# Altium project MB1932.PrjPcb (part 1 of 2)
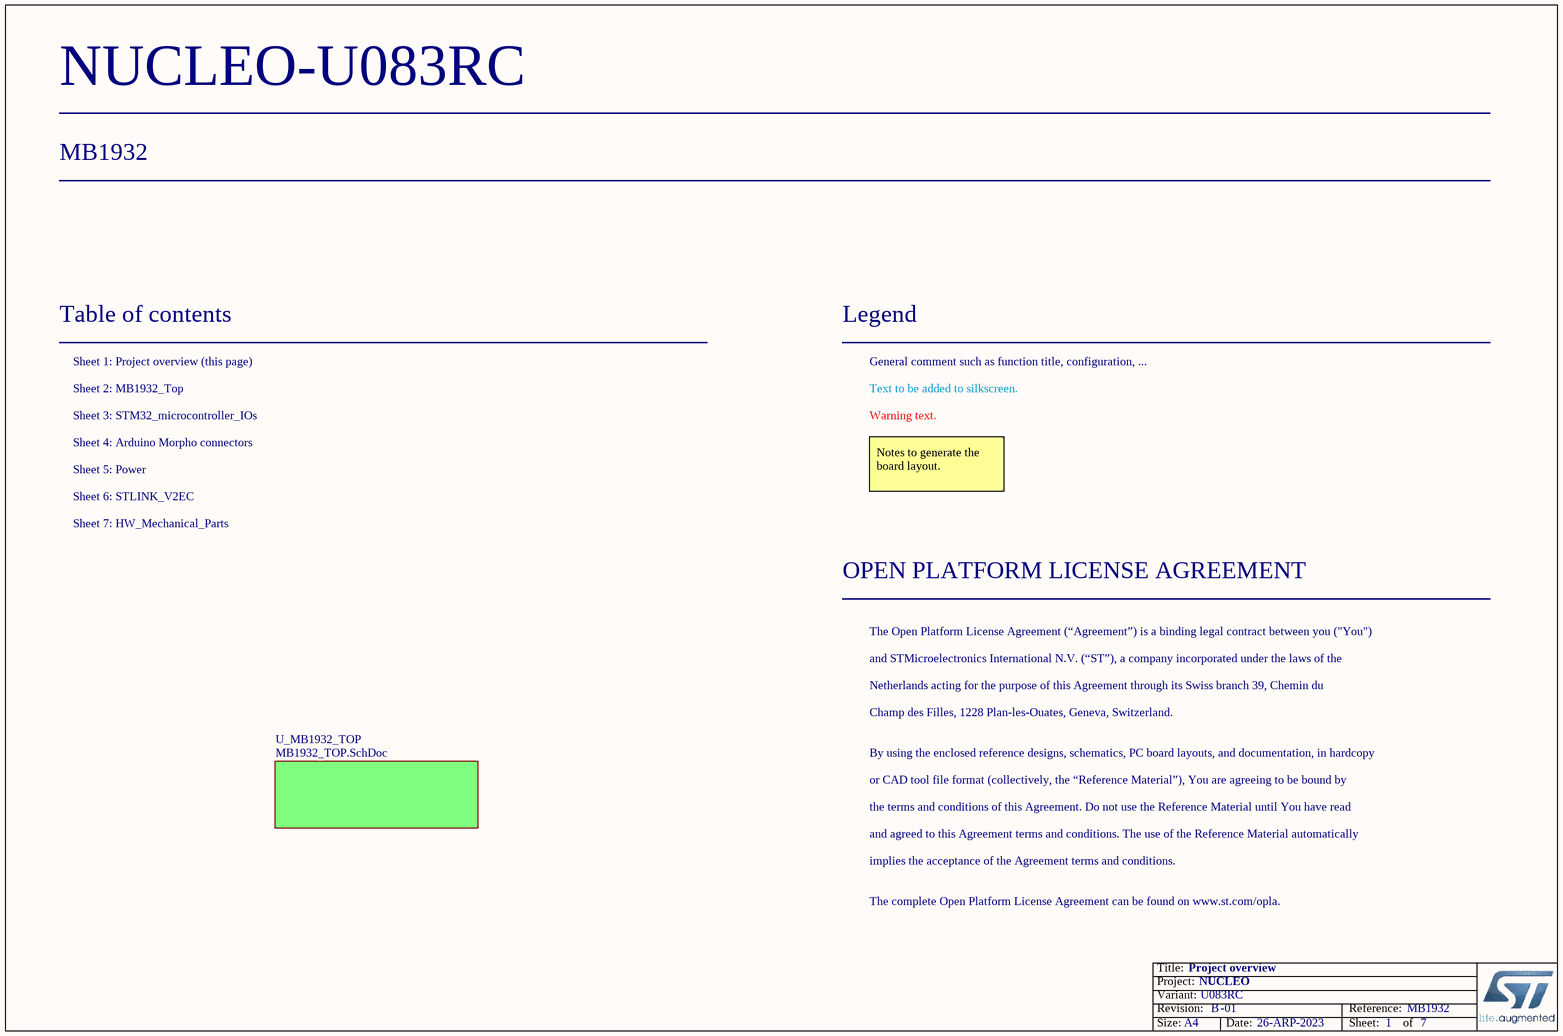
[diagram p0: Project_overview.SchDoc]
VariantName: U083RC; Board_Reference: MB1932; Board_PCB_Revision: B; Board_Name: NUCLEO; Board_Document_Date: 26-ARP-2023; Board_Assembly_Revision: 01
7 sheets, 197 parts. Net scope: flat (ports and power ports of the same name join across sheets).
Board file: MB1932.PcbDoc
Sheets:
  Project_overview.SchDoc
    U_MB1932_TOP = MB1932_TOP.SchDoc
      Power = Power.SchDoc
      HW_Mechanical_Parts = HW_Mechanical_Parts.SchDoc
      U_STM32_microcontroller_IOs = STM32_microcontroller_IOs.SchDoc
      U_Arduino_Morpho_connectors = Arduino_Morpho_connectors.SchDoc
      U_STLINK_V2EC = STLINK_V2EC.SchDoc

## Sheet Project_overview.SchDoc: Project overview
size A4; Date: Not used; ApprovedBy: Not used; CheckedBy: Not used; Author: Not used; CompanyName: STMicroelectronics; DrawnBy: Not used; Engineer: Not used; Organization: Not used; Address1: Not used; Address2: Not used; Address3: Not used; Address4: Not used; DocumentNumber: 1; Revision: Not used; SheetNumber: 1; SheetTotal: 7

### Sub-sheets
U_MB1932_TOP = MB1932_TOP.SchDoc: no entries

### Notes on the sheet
- Table of contents
- Sheet 1: Project overview (this page)
- Legend
- General comment such as function title, configuration, ...
- Sheet 2: MB1932_Top
- Sheet 4: Arduino Morpho connectors
- Sheet 3: STM32_microcontroller_IOs
- Text to be added to silkscreen.
- Warning text.
- Sheet 5: Power
- Sheet 6: STLINK_V2EC
- Notes to generate the board layout.
- Sheet 7: HW_Mechanical_Parts
- OPEN PLATFORM LICENSE AGREEMENT
- The Open Platform License Agreement (“Agreement”) is a binding legal contract between you ("You")
- and STMicroelectronics International N.V. (“ST”), a company incorporated under the laws of the
- Netherlands acting for the purpose of this Agreement through its Swiss branch 39, Chemin du
- Champ des Filles, 1228 Plan-les-Ouates, Geneva, Switzerland.
- By using the enclosed reference designs, schematics, PC board layouts, and documentation, in hardcopy
- or CAD tool file format (collectively, the “Reference Material”), You are agreeing to be bound by
- the terms and conditions of this Agreement. Do not use the Reference Material until You have read
- and agreed to this Agreement terms and conditions. The use of the Reference Material automatically
- implies the acceptance of the Agreement terms and conditions.
- The complete Open Platform License Agreement can be found on www.st.com/opla.

## Sheet MB1932_TOP.SchDoc: TOP
size A4; CompanyName: STMicroelectronics; Organization: Microcontrollers Division; SheetNumber: 2; SheetTotal: 7
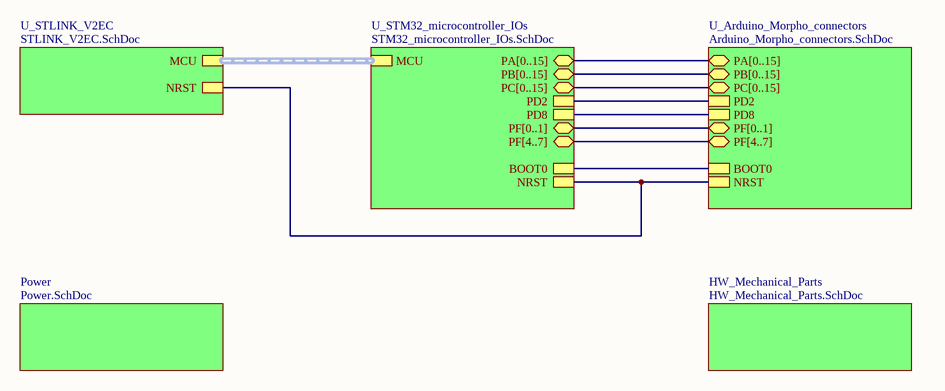
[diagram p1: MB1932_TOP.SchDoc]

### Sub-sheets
HW_Mechanical_Parts = HW_Mechanical_Parts.SchDoc: no entries
Power = Power.SchDoc: no entries
U_Arduino_Morpho_connectors = Arduino_Morpho_connectors.SchDoc: NRST, PA[0..15] (bidir), PB[0..15] (bidir), PD2, PC[0..15] (bidir), PD8, PF[4..7] (bidir), BOOT0, PF[0..1] (bidir)
U_STLINK_V2EC = STLINK_V2EC.SchDoc: MCU (harness MCU), NRST
U_STM32_microcontroller_IOs = STM32_microcontroller_IOs.SchDoc: PA[0..15] (bidir), PB[0..15] (bidir), PD2, PC[0..15] (bidir), MCU (harness MCU), PF[0..1] (bidir), PF[4..7] (bidir), BOOT0, PD8, NRST

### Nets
(unnamed): sheet U_STM32_microcontroller_IOs/PD2, sheet U_Arduino_Morpho_connectors/PD2
(unnamed): sheet U_STM32_microcontroller_IOs/BOOT0, sheet U_Arduino_Morpho_connectors/BOOT0  [a separate net that carries the same name]
(unnamed): sheet U_STM32_microcontroller_IOs/PD8, sheet U_Arduino_Morpho_connectors/PD8  [a separate net that carries the same name]
(unnamed): sheet U_STM32_microcontroller_IOs/NRST, sheet U_Arduino_Morpho_connectors/NRST, sheet U_STLINK_V2EC/NRST  [a separate net that carries the same name]

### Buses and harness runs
bus sheet U_Arduino_Morpho_connectors/PA[0..15] = sheet U_STM32_microcontroller_IOs/PA[0..15]
bus sheet U_Arduino_Morpho_connectors/PB[0..15] = sheet U_STM32_microcontroller_IOs/PB[0..15]
bus sheet U_Arduino_Morpho_connectors/PC[0..15] = sheet U_STM32_microcontroller_IOs/PC[0..15]
bus sheet U_Arduino_Morpho_connectors/PF[0..1] = sheet U_STM32_microcontroller_IOs/PF[0..1]
bus sheet U_Arduino_Morpho_connectors/PF[4..7] = sheet U_STM32_microcontroller_IOs/PF[4..7]
harness sheet U_STLINK_V2EC/MCU = sheet U_STM32_microcontroller_IOs/MCU

## Sheet Power.SchDoc: Power
size A4; CompanyName: STMicroelectronics; Organization: Microcontrollers Division; SheetNumber: 5; SheetTotal: 7
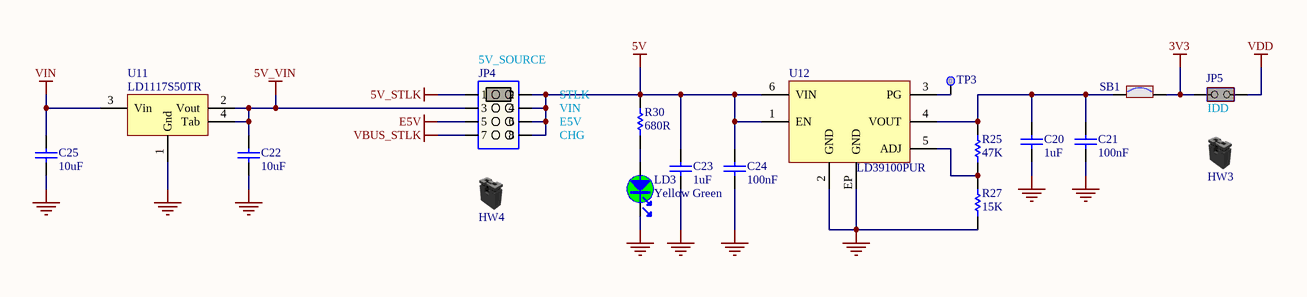
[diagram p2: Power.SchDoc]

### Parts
C20  value 1uF  [C0603]  (hidden comment: Capacitor)
C21  value 100nF  [C0402]  (hidden comment: Capacitor)
C22  value 10uF  [C0805]  (hidden comment: Capacitor)
C23  value 1uF  [C0603]  (hidden comment: Capacitor)
C24  value 100nF  [C0402]  (hidden comment: Capacitor)
C25  value 10uF  [C0805]  (hidden comment: Capacitor)
HW3  Shunt Black 2.54mm  (value not drawn)  (mechanical)
HW4  Shunt Black 2.54mm  (value not drawn)  (mechanical)
JP4  Jumper_Header 4x2 Fitted 1-2  [CON_SAMTEC_TSW-104-07-X-D]  (value not drawn)
JP5  Jumper_Header 2x1 Fitted  [CON_SAMTEC_TSW-102-07-G-S]  (value not drawn)
LD3  value Yellow Green  [LED_0402_EVERLIGHT_16-213SYGC/S530-E3-TR8 _YELLOW-GREEN_1A2K_H0P45]  (hidden comment: LED_green)
R25  value 47K  [R0402]  (hidden comment: Resistor)
R27  value 15K  [R0402]  (hidden comment: Resistor)
R30  value 680R  [R0402]  (hidden comment: Resistor)
SB1  SB_ON  [SOLDER-BRIDGE_R0603-0R]  (value not drawn)
TP3  Test Point  [TP_SMD_1MM]  (value not drawn)  (no BOM)
U11  LD1117S50TR  [REG_SOT223-TAB]
U12  LD39100PUR  [ICC_DFN6-EPAD_3X3_P095]

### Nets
3V3: JP5.2(NO) SB1.2
5V: C23.2 C24.2 JP4.2 JP4.4 JP4.6 JP4.8 R30.1 U12.1(EN) U12.6(VIN)
5V_STLK: JP4.1
5V_VIN: C22.2 JP4.3 U11.2(Vout) U11.4(Tab)
E5V: JP4.5
GND: C20.1 C21.1 C22.1 C23.1 C24.1 C25.1 LD3.2 R27.1 U11.1(Gnd) U12.2(GND) U12.EP(GND)
VBUS_STLK: JP4.7
VDD: JP5.1(COMMON)
VIN: C25.2 U11.3(Vin)
NetC20_2: C20.2 C21.2 R25.2 SB1.1 U12.4(VOUT)
NetLD3_1: LD3.1 R30.2
NetR25_1: R25.1 R27.2 U12.5(ADJ)
NetTP3_1: TP3.1 U12.3(PG)

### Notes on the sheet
- (near JP4) 5V_SOURCE
- CHG
- E5V
- VIN
- STLK
- (near JP5) IDD

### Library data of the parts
C20 C23 = MCD-00010: Capacitor, MLCC, 1uF, 16V, X5R, +/-10%, 0603, T=0.8mm; Manufacturer_Part_Number: CC0603KRX5R7BB105; Manufacturer: YAGEO; Alternate_Manufacturer_Part_Number: GCM155R71C104KA55D; Alternate_Manufacturer: MURATA; Part_Preference: Recommended; ECCN_US: EAR99; ECCN_EU: NEC; Provided_By: SUBCO; Component_Country_Of_Origin: China; ShowFields: YES; ID: 2470
C21 C24 = MCD-00006: Capacitor, MLCC, 100nF, 16V, X7R, +/-10%, 0402, T=0.5mm; Manufacturer_Part_Number: CC0402KRX7R7BB104; Manufacturer: YAGEO; Alternate_Manufacturer_Part_Number: GCM155R71C104KA55D; Alternate_Manufacturer: MURATA; Part_Preference: Recommended; ECCN_US: EAR99; ECCN_EU: NEC; Provided_By: SUBCO; Order_Code_RS: 616-9701; Component_Country_Of_Origin: China; ShowFields: YES; ID: 2474
C22 C25 = MCD-00014: Capacitor, MLCC, 10uF, 25V, X5R, +/-10%, 0805, T=0.85mm; Manufacturer_Part_Number: CC0805KRX5R8BB106; Manufacturer: YAGEO; Alternate_Manufacturer_Part_Number: GCM155R71C104KA55D; Alternate_Manufacturer: MURATA; Part_Preference: Recommended; Full_Alternate_Internal_Part_Number: MCD-02385; Partial_Alternate_Internal_Part_Number: MCD-03053; ECCN_US: EAR99; ECCN_EU: NEC; Provided_By: SUBCO; Component_Country_Of_Origin: China; ShowFields: YES; ID: 2468
HW3 HW4 = MCD-00043: SHUNT 2.54mm BLACK; Manufacturer_Part_Number: SNT-100-BK-G; Manufacturer: SAMTEC; Part_Type: Misc; Part_Preference: Recommended; Full_Alternate_Internal_Part_Number: MCD-02388; Value: SNT-100-BK-G; Component_Country_Of_Origin: China, Costa Rica, Malaysia, United States, Vietnam; ShowFields: YES; ID: 2551
JP4 = MCD-00686: Header, 4x2, 2.54mm, VR, TH, T=5.84mm/2.54mm; Part_Type: Connector; Manufacturer_Part_Number: TSW-104-07-G-D; Manufacturer: SAMTEC; Part_Preference: Recommended; Order_Code_RS: 161-2260; Component_Country_Of_Origin: China, Costa Rica, Malaysia, United States, Vietnam; ShowFields: YES; ID: 3062
JP5 = MCD-00683: Header, 2x1, 2.54mm, VR, TH, T=5.84mm/2.54mm; Part_Type: Connector; Manufacturer_Part_Number: TSW-102-07-G-S; Manufacturer: SAMTEC; Alternate_Manufacturer_Part_Number: 313102S111116; Alternate_Manufacturer: LIANYI; Part_Preference: Recommended; Full_Alternate_Internal_Part_Number: MCD-02389; Partial_Alternate_Internal_Part_Number: MCD-02957; Provided_By: SUBCO; Order_Code_RS: 155-5312; Component_Country_Of_Origin: China, Costa Rica, Malaysia, United States, Vietnam; ShowFields: YES; ID: 3057
LD3 = MCD-02330: LED, Yellow Green, 2V, 25mA, 0402, 0.45mm; Part_Type: Display; Manufacturer_Part_Number: 16-213SYGC/S530-E3/TR8; Manufacturer: EVERLIGHT; Alternate_Manufacturer_Part_Number: LG Q396-PS-35; Alternate_Manufacturer: OSRAM OPTO SEMICONDUCTORS; Part_Preference: Recommended; Provided_By: SUBCO; Component_Country_Of_Origin: China; ShowFields: YES; ID: 4436
R25 = MCD-00063: Resistor, 47K, 0402, +/-1%, 1/16W; Part_Preference: Recommended; Manufacturer: YAGEO; Manufacturer_Part_Number: RC0402FR-0747KL; Component_Country_Of_Origin: China; ShowFields: YES; ID: 2528
R27 = MCD-01943: Resistor, 15K, 0402, +/-1%, 1/16W; Part_Preference: Recommended; Manufacturer: YAGEO; Manufacturer_Part_Number: RC0402FR-0715KL; Order_Code_RS: 618-6009; Component_Country_Of_Origin: China; ShowFields: YES; ID: 4043
R30 = MCD-00507: Resistor, 680R, 0402, +/-1%, 1/16W; Manufacturer_Part_Number: RC0402FR-07680RL; Manufacturer: YAGEO; Alternate_Manufacturer_Part_Number: RT0402FRE07100KL; Part_Preference: Recommended; ECCN_US: EAR99; ECCN_EU: NEC; Provided_By: SUBCO; Component_Country_Of_Origin: China; ShowFields: YES; ID: 3238
SB1 = MCD-00071: Solder Bridge ON; Part_Type: Misc; Manufacturer_Part_Number: RC0603JR-070RL; Manufacturer: YAGEO; Part_Preference: Recommended; Provided_By: SUBCO; ShowFields: YES; ID: 2521
TP3 = MCD-00074: Test Point 1mm; Part_Type: Misc; Part_Preference: Recommended; ShowFields: YES; ID: 2518
U11 = MCD-00088: IC REG LDO 5V 0.8A SOT223; Manufacturer: STMICROELECTRONICS; BMS_Part_Number: 9176133; Part_Preference: Recommended; Manufacturer_HQ_COO: EU; ECCN_US: EAR99; ECCN_EU: NEC; Provided_By: SUBCO with ST control; Component_Country_Of_Origin: China; ShowFields: YES; ID: 2503
U12 = MCD-03339: LDO, output 1.5 to 5.5V 1A adjustable; Part_Type: IC; Part_Preference: Recommended; Manufacturer: STMICROELECTRONICS; ShowFields: YES; ID: 5455

## Sheet HW_Mechanical_Parts.SchDoc: HW Mechanical parts
size A4; SheetNumber: 7; SheetTotal: 7
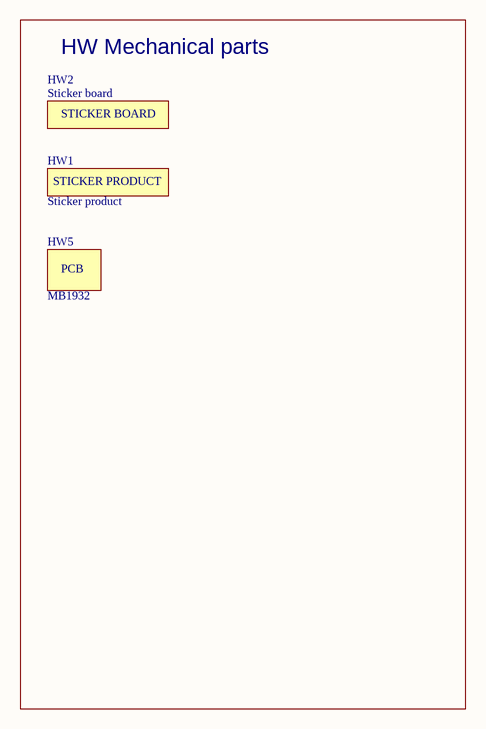
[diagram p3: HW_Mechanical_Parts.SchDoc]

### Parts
HW1  value Sticker product  [STICKER_PRODUCT_25X9]  (hidden comment: STICKER_PRODUCT)  (no BOM)
HW2  value Sticker board  [STICKER_BOARD_25X9]  (hidden comment: STICKER_BOARD)  (no BOM)
HW5  value MB1932  (hidden comment: PCB)  (no BOM)

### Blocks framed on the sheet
HW Mechanical parts: HW1 HW2 HW5

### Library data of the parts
HW1 = MCD-00547: Sticker product 25x9 mm; Part_Type: Misc; Part_Preference: Recommended; ShowFields: YES; ID: 3197
HW2 = MCD-00235: Sticker Board 25x9 mm; Part_Type: Misc; Part_Preference: Recommended; ShowFields: YES; ID: 2632
HW5 = MCD-03167: MB1932 PCB; Part_Preference: Recommended; ShowFields: YES; ID: 5283

## Sheet STM32_microcontroller_IOs.SchDoc: STM32_microcontroller_IOs
size A4; CompanyName: STMicroelectronics; Organization: Microcontrollers Division; SheetNumber: 3; SheetTotal: 7
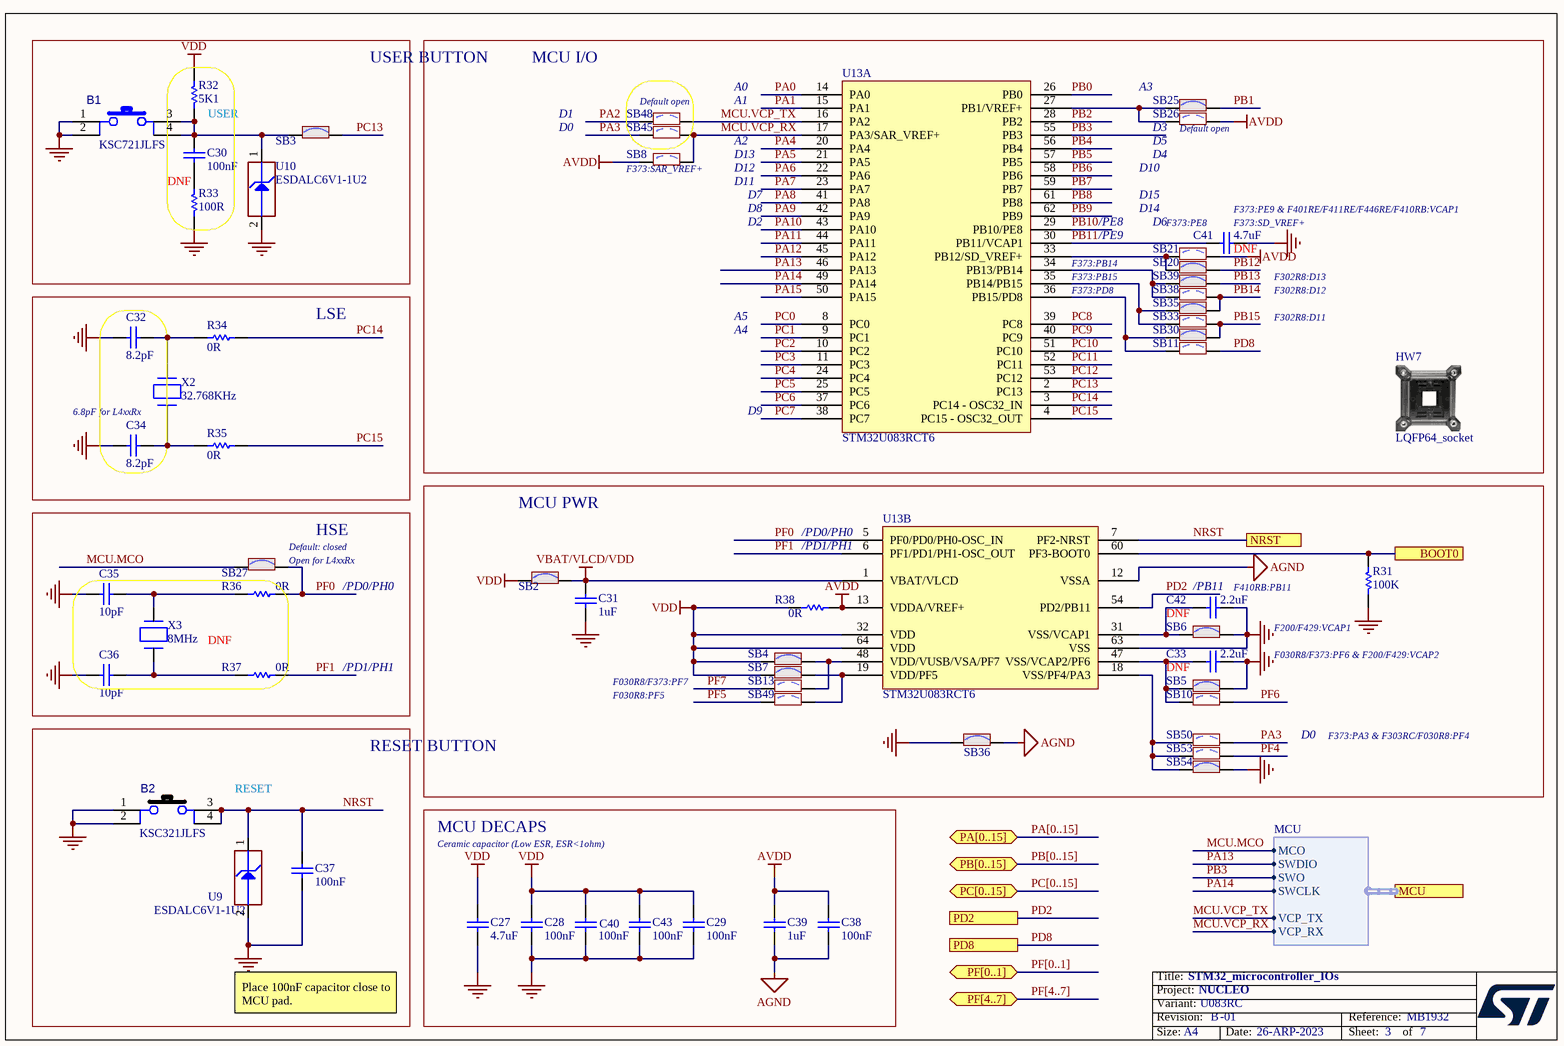
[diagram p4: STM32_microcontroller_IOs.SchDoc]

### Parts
B1  value KSC721JLFS  [SWI_C&K_KSC721JLFS_BLUE]  (hidden comment: SW_BLUE_KSC721JLFS)
B2  value KSC321JLFS  [SWI_C&K_KSC321JLFS_BLACK]  (hidden comment: SW_BLACK_KSC321JLFS)
C27  value 4.7uF  [C0603_H0P8]  (hidden comment: Capacitor)
C28  value 100nF  [C0402]  (hidden comment: Capacitor)
C29  value 100nF  [C0402]  (hidden comment: Capacitor)
C30  value 100nF  [C0402]  (hidden comment: Capacitor)
C31  value 1uF  [C0603]  (hidden comment: Capacitor)
C32  value 8.2pF  [C0402]  (hidden comment: Capacitor)
C33  value 2.2uF  [C0402]  (hidden comment: Capacitor)
C34  value 8.2pF  [C0402]  (hidden comment: Capacitor)
C35  value 10pF  [C0402]  (hidden comment: Capacitor)
C36  value 10pF  [C0402]  (hidden comment: Capacitor)
C37  value 100nF  [C0402]  (hidden comment: Capacitor)
C38  value 100nF  [C0402]  (hidden comment: Capacitor)
C39  value 1uF  [C0603]  (hidden comment: Capacitor)
C40  value 100nF  [C0402]  (hidden comment: Capacitor)
C41  value 4.7uF  [C0603_H0P8]  (hidden comment: Capacitor)
C42  value 2.2uF  [C0402]  (hidden comment: Capacitor)
C43  value 100nF  [C0402]  (hidden comment: Capacitor)
HW7  value LQFP64_socket  (hidden comment: SOCKET_LQFP64)  (mechanical)
R31  value 100K  [R0402]  (hidden comment: Resistor)
R32  value 5K1  [R0402]  (hidden comment: Resistor)
R33  value 100R  [R0402]  (hidden comment: Resistor)
R34  value 0R  [R0402]  (hidden comment: Resistor)
R35  value 0R  [R0402]  (hidden comment: Resistor)
R36  value 0R  [R0402]  (hidden comment: Resistor)
R37  value 0R  [R0402]  (hidden comment: Resistor)
R38  value 0R  [R0603]  (hidden comment: Resistor)
SB2  SB_ON  [SOLDER-BRIDGE_R0603-0R]  (value not drawn)
SB3  SB_ON  [SOLDER-BRIDGE_R0603-0R]  (value not drawn)
SB4  SB_ON  [SOLDER-BRIDGE_R0603-0R]  (value not drawn)
SB5  SB_ON  [SOLDER-BRIDGE_R0603-0R]  (value not drawn)
SB6  SB_ON  [SOLDER-BRIDGE_R0603-0R]  (value not drawn)
SB7  SB_ON  [SOLDER-BRIDGE_R0603-0R]  (value not drawn)
SB8  SB_OFF  [SOLDER-BRIDGE_R0603-0R]  (value not drawn)
SB10  SB_OFF  [SOLDER-BRIDGE_R0603-0R]  (value not drawn)
SB11  SB_OFF  [SOLDER-BRIDGE_R0603-0R]  (value not drawn)
SB13  SB_OFF  [SOLDER-BRIDGE_R0603-0R]  (value not drawn)
SB20  SB_ON  [SOLDER-BRIDGE_R0603-0R]  (value not drawn)
SB21  SB_OFF  [SOLDER-BRIDGE_R0603-0R]  (value not drawn)
SB25  SB_ON  [SOLDER-BRIDGE_R0603-0R]  (value not drawn)
SB26  SB_OFF  [SOLDER-BRIDGE_R0603-0R]  (value not drawn)
SB27  SB_ON  [SOLDER-BRIDGE_R0603-0R]  (value not drawn)
SB30  SB_ON  [SOLDER-BRIDGE_R0603-0R]  (value not drawn)
SB33  SB_OFF  [SOLDER-BRIDGE_R0603-0R]  (value not drawn)
SB35  SB_ON  [SOLDER-BRIDGE_R0603-0R]  (value not drawn)
SB36  SB_ON  [SOLDER-BRIDGE_R0603-0R]  (value not drawn)
SB38  SB_OFF  [SOLDER-BRIDGE_R0603-0R]  (value not drawn)
SB39  SB_ON  [SOLDER-BRIDGE_R0603-0R]  (value not drawn)
SB45  SB_OFF  [SOLDER-BRIDGE_R0603-0R]  (value not drawn)
SB48  SB_OFF  [SOLDER-BRIDGE_R0603-0R]  (value not drawn)
SB49  SB_OFF  [SOLDER-BRIDGE_R0603-0R]  (value not drawn)
SB50  SB_OFF  [SOLDER-BRIDGE_R0603-0R]  (value not drawn)
SB53  SB_OFF  [SOLDER-BRIDGE_R0603-0R]  (value not drawn)
SB54  SB_ON  [SOLDER-BRIDGE_R0603-0R]  (value not drawn)
U9  value ESDALC6V1-1U2  [ESD_ST0201]  (hidden comment: ESD-TRANSIL)
U10  value ESDALC6V1-1U2  [ESD_ST0201]  (hidden comment: ESD-TRANSIL)
U13  value STM32U083RCT6  [ICC_LQFP64_10X10_P050_SOCKET_YAMAICHI_IC149-064-069-B5_NM]  (hidden comment: STM32_MCU_LQFP64)  (parts A,B of 2)
X2  value 32.768KHz  [CRY_NX2012SA_2P]  (hidden comment: XTAL_2_PINS)
X3  value 8MHz  [CRY_NX3225GD_2P]  (hidden comment: XTAL_2_PINS)

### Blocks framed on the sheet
USER BUTTON: B1 C30 R32 R33 SB3 U10
MCU I/O: C41 HW7 SB8 SB11 SB20 SB21 SB25 SB26 SB30 SB33 SB35 SB38 SB39 U13
Default open: SB45 SB48
LSE: C32 C34 R34 R35 X2
HSE: SB27
MCU PWR: C31 C33 C42 R31 R38 SB2 SB4-SB7 SB10 SB13 SB36 SB49 SB50 SB53 SB54 U13
DNF: C35 C36 R36 R37 X3
RESET BUTTON: B2 C37 U9
MCU DECAPS: C27-C29 C38-C40 C43

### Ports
BOOT0, MCU (harness MCU), NRST, PA[0..15] (bidir), PB[0..15] (bidir), PC[0..15] (bidir), PD2, PD8, PF[0..1] (bidir), PF[4..7] (bidir)

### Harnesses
MCU: MCO, SWDIO, SWO, VCP_TX, SWCLK, VCP_RX

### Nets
AGND: C38.1 C39.2 SB36.2 U13.12(VSSA)
AVDD: C38.2 C39.1 R38.2 SB8.1 SB21.2 SB26.2 U13.13(VDDA/VREF+)
GND: B1.1 B1.2 B2.1 B2.2 C27.1 C28.1 C29.1 C31.2 C32.1 C33.2 C34.1 C35.1 C36.1 C37.1 C40.1 C41.2 C42.2 C43.1 R31.2 R33.2 SB5.2 SB6.2 SB36.1 SB54.2 U9.2(GND) U10.2(GND) U13.63(VSS)
VBAT/VLCD/VDD: C31.1 SB2.2 U13.1(VBAT/VLCD)
VDD: C27.2 C28.2 C29.2 C40.2 C43.2 R32.2 R38.1 SB2.1 SB4.1 SB7.1 U13.32(VDD) U13.64(VDD)
BOOT0: R31.1 U13.60(PF3-BOOT0) ; port BOOT0
MCU.MCO: SB27.1 ; port MCU.MCO
MCU.VCP_RX: SB8.2 SB45.2 U13.17(PA3/SAR_VREF+) ; port MCU.VCP_RX
MCU.VCP_TX: SB48.2 U13.16(PA2) ; port MCU.VCP_TX
NRST: B2.3 B2.4 C37.2 U9.1(IO1) U13.7(PF2-NRST) ; port NRST
PA0: U13.14(PA0)
PA1: U13.15(PA1)
PA2: SB48.1
PA3: SB45.1 SB50.2
PA4: U13.20(PA4)
PA5: U13.21(PA5)
PA6: U13.22(PA6)
PA7: U13.23(PA7)
PA8: U13.41(PA8)
PA9: U13.42(PA9)
PA10: U13.43(PA10)
PA11: U13.44(PA11)
PA12: U13.45(PA12)
PA13: U13.46(PA13) ; port MCU.SWDIO  [project net MCU.SWDIO]
PA14: U13.49(PA14) ; port MCU.SWCLK  [project net MCU.SWCLK]
PA15: U13.50(PA15)
PB0: U13.26(PB0)
PB1: SB25.2
PB2: U13.28(PB2)
PB3: U13.55(PB3) ; port MCU.SWO  [project net MCU.SWO]
PB4: U13.56(PB4)
PB5: U13.57(PB5)
PB6: U13.58(PB6)
PB7: U13.59(PB7)
PB8: U13.61(PB8)
PB9: U13.62(PB9)
PB10: U13.29(PB10/PE8)
PB11: C41.1 U13.30(PB11/VCAP1)
PB12: SB20.2
PB13: SB39.2
PB14: SB35.2 SB38.2
PB15: SB30.2 SB33.2
PC0: U13.8(PC0)
PC1: U13.9(PC1)
PC2: U13.10(PC2)
PC3: U13.11(PC3)
PC4: U13.24(PC4)
PC5: U13.25(PC5)
PC6: U13.37(PC6)
PC7: U13.38(PC7)
PC8: U13.39(PC8)
PC9: U13.40(PC9)
PC10: U13.51(PC10)
PC11: U13.52(PC11)
PC12: U13.53(PC12)
PC13: SB3.2 U13.2(PC13)
PC14: R34.2 U13.3(PC14_-_OSC32_IN)
PC15: R35.2 U13.4(PC15_-_OSC32_OUT)
PD2: U13.54(PD2/PB11) ; port PD2
PD8: SB11.2 ; port PD8
PF0: R36.2 SB27.2 U13.5(PF0/PD0/PH0-OSC_IN)
PF1: R37.2 U13.6(PF1/PD1/PH1-OSC_OUT)
PF4: SB53.2
PF5: SB49.1
PF6: SB10.2
PF7: SB13.1
NetB1_3: B1.3 B1.4 C30.2 R32.1 SB3.1 U10.1(IO1)
NetC30_1: C30.1 R33.1
NetC32_2: C32.2 R34.1 X2.2(X2)
NetC33_1: C33.1 SB5.1 SB10.1 U13.47(VSS/VCAP2/PF6)
NetC34_2: C34.2 R35.1 X2.1(X1)
NetC35_2: C35.2 R36.1 X3.2(X2)
NetC36_2: C36.2 R37.1 X3.1(X1)
NetC42_1: C42.1 SB6.1 U13.31(VSS/VCAP1)
NetSB4_2: SB4.2 SB13.2 U13.48(VDD/VUSB/VSA/PF7)
NetSB7_2: SB7.2 SB49.2 U13.19(VDD/PF5)
NetSB11_1: SB11.1 SB30.1 U13.36(PB15/PD8)
NetSB20_1: SB20.1 SB21.1 U13.33(PB12/SD_VREF+)
NetSB25_1: SB25.1 SB26.1 U13.27(PB1/VREF+)
NetSB33_1: SB33.1 SB35.1 U13.35(PB14/PB15)
NetSB38_1: SB38.1 SB39.1 U13.34(PB13/PB14)
NetSB50_1: SB50.1 SB53.1 SB54.1 U13.18(VSS/PF4/PA3)

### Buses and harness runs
bus PA[0..15] = port PA[0..15]
bus PB[0..15] = port PB[0..15]
bus PC[0..15] = port PC[0..15]
bus PF[0..1] = port PF[0..1]
bus PF[4..7] = port PF[4..7]

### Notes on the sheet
- (near R32) USER
- D1
- A0
- A1
- A3
- DNF
- D0
- (near SB8) F373:SAR_VREF+
- A2
- D12
- D11
- D13
- D10
- D4
- D3
- D5
- (near SB26) Default open
- D2
- D7
- D8
- /PE9
- /PE8
- D14
- D15
- D6
- F373:PE8
- (near C41) F373:SD_VREF+
- (near C41) DNF
- (near C41) F373:PE9 & F401RE/F411RE/F446RE/F410RB:VCAP1
- A5
- F373:PB14
- F373:PB15
- (near U13) F373:PD8
- F302R8:D13
- F302R8:D12
- F302R8:D11
- A4
- 6.8pF for L4xxRx
- D9
- (near SB27) Default: closed
- (near SB27) Open for L4xxRx
- /PD0/PH0
- (near U13) /PD0/PH0
- (near U13) /PD1/PH1
- (near C42) /PB11
- (near C42) F410RB:PB11
- F200/F429:VCAP1
- F030R8/F373:PF6 & F200/F429:VCAP2
- /PD1/PH1
- F030R8:PF5
- F030R8/F373:PF7
- RESET
- F373:PA3 & F303RC/F030R8:PF4
- Ceramic capacitor (Low ESR, ESR<1ohm)
- Place 100nF capacitor close to MCU pad.

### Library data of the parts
B1 = MCD-01800: Switch HW BLUE High4.3mm 2.25 Newtons, BEND type; Part_Type: Misc; Part_Preference: Recommended; Manufacturer: C&K; Component_Country_Of_Origin: France; ShowFields: YES; ID: 3900
B2 = MCD-01799: Switch HW BLACK High3.5mm 2Newtons, BEND type; Part_Type: Misc; Part_Preference: Recommended; Manufacturer: C&K; Component_Country_Of_Origin: France; ShowFields: YES; ID: 3899
C27 = MCD-01721: Capacitor, MLCC, 4.7uF, 10V, X5R, +/-10%, 0603, T=0.8mm; Part_Preference: Recommended; Manufacturer: YAGEO; Manufacturer_Part_Number: CC0603KRX5R6BB475; Component_Country_Of_Origin: China; ShowFields: YES; ID: 3821
C28 C29 C38 C40 C43 = MCD-00006: Capacitor, MLCC, 100nF, 16V, X7R, +/-10%, 0402, T=0.5mm; Manufacturer_Part_Number: CC0402KRX7R7BB104; Manufacturer: YAGEO; Part_Preference: Recommended; Alternate_Manufacturer_Part_Number: GCM155R71C104KA55D; Alternate_Manufacturer: MURATA; Order_Code_RS: 616-9701; Component_Country_Of_Origin: China; ShowFields: YES; ID: 2474; ECCN_US: EAR99; ECCN_EU: NEC; Provided_By: SUBCO
C30 = MCD-00006: Capacitor, MLCC, 100nF, 16V, X7R, +/-10%, 0402, T=0.5mm; Manufacturer_Part_Number: CC0402KRX7R7BB104; Manufacturer: YAGEO; Part_Preference: Recommended; Order_Code_RS: 616-9701; Component_Country_Of_Origin: China; ShowFields: YES; ID: 2474
C31 C39 = MCD-00010: Capacitor, MLCC, 1uF, 16V, X5R, +/-10%, 0603, T=0.8mm; Manufacturer_Part_Number: CC0603KRX5R7BB105; Manufacturer: YAGEO; Part_Preference: Recommended; Alternate_Manufacturer_Part_Number: GCM155R71C104KA55D; Alternate_Manufacturer: MURATA; Component_Country_Of_Origin: China; ShowFields: YES; ID: 2470; ECCN_US: EAR99; ECCN_EU: NEC; Provided_By: SUBCO
C32 C34 = MCD-01932: Capacitor, MLCC, 8.2pF, 50V, NPO, +/-0.25pF, 0402, T=0.5mm; Manufacturer_Part_Number: CC0402CRNPO9BN8R2; Manufacturer: YAGEO; Alternate_Manufacturer_Part_Number: GCM155R71C104KA55D; Alternate_Manufacturer: MURATA; Part_Preference: Recommended; ECCN_US: EAR99; ECCN_EU: NEC; Provided_By: SUBCO; Component_Country_Of_Origin: China; ShowFields: YES; ID: 4032
C33 C42 = MCD-02606: Capacitor, MLCC, 2.2uF, 6.3V, X5R, +/-10%, 0402, T=0.5mm; Part_Preference: Recommended; Manufacturer: YAGEO; Manufacturer_Part_Number: CC0402KRX5R5BB225; Order_Code_RS: 1992205; ShowFields: YES; ID: 4712
C35 C36 = MCD-00015: Capacitor, MLCC, 10pF, 50V, NPO, +/-5%, 0402, T=0.5mm; Manufacturer_Part_Number: CC0402JRNPO9BN100; Manufacturer: YAGEO; Part_Preference: Recommended; Order_Code_RS: 616-9256; Component_Country_Of_Origin: China; ShowFields: YES; ID: 2465
C37 = MCD-00006: Capacitor, MLCC, 100nF, 16V, X7R, +/-10%, 0402, T=0.5mm; Part_Preference: Recommended; Manufacturer: YAGEO; Manufacturer_Part_Number: CC0402KRX7R7BB104; Alternate_Manufacturer_Part_Number: GCM155R71C104KA55D; Alternate_Manufacturer: MURATA; Order_Code_RS: 616-9701; Component_Country_Of_Origin: China; ShowFields: YES; ID: 2474; ECCN_US: EAR99; ECCN_EU: NEC; Provided_By: SUBCO
C41 = MCD-01721: Capacitor, MLCC, 4.7uF, 10V, X5R, +/-10%, 0603, T=0.8mm; Part_Preference: Recommended; Manufacturer: YAGEO; Manufacturer_Part_Number: CC0603KRX5R6BB475; ShowFields: YES; ID: 3821; Component_Country_Of_Origin: China
HW7 = MCD-01253: Socket_IC, LQFP64, pitch 0.5mm, with positioning pins; Manufacturer_Part_Number: IC149-064-169-B5; Manufacturer: YAMAICHI; Part_Preference: Recommended; Component_Country_Of_Origin: Unknown; ShowFields: YES; ID: 3244
R31 = MCD-00059: Resistor, 100K, 0402, +/-1%, 1/16W; Manufacturer_Part_Number: RC0402FR-07100KL; Manufacturer: YAGEO; Part_Preference: Recommended; Component_Country_Of_Origin: China; ShowFields: YES; ID: 2533
R32 = MCD-00333: Resistor, 5K1, 0402, +/-1%, 1/16W; Manufacturer_Part_Number: RC0402FR-075K1L; Manufacturer: YAGEO; Part_Preference: Recommended; Component_Country_Of_Origin: China; ShowFields: YES; ID: 2944
R33 = MCD-00067: Resistor, 100R, 0402, +/- 1%, 1/16W; Manufacturer_Part_Number: RC0402FR-07100RL; Manufacturer: YAGEO; Part_Preference: Recommended; Component_Country_Of_Origin: China; ShowFields: YES; ID: 2527
R34 R35 = MCD-00052: Resistor, 0R, 0402, +/-5%, 1/16W; Manufacturer_Part_Number: RC0402JR-070RL; Manufacturer: YAGEO; Alternate_Manufacturer_Part_Number: RT0402FRE07100KL; Part_Preference: Recommended; ECCN_US: EAR99; ECCN_EU: NEC; Provided_By: SUBCO; Order_Code_RS: 618-5804; Component_Country_Of_Origin: China; ShowFields: YES; ID: 2540
R36 R37 = MCD-00052: Resistor, 0R, 0402, +/-5%, 1/16W; Manufacturer_Part_Number: RC0402JR-070RL; Manufacturer: YAGEO; Alternate_Manufacturer_Part_Number: RT0402FRE07100KL; Part_Preference: Recommended; Provided_By: SUBCO; ECCN_US: EAR99; ECCN_EU: NEC; Order_Code_RS: 618-5804; Component_Country_Of_Origin: China; ShowFields: YES; ID: 2540
R38 = MCD-00056: Resistor, 0R, 0603, +/-5%, 1/10W; Manufacturer_Part_Number: RC0603JR-070RL; Manufacturer: YAGEO; Part_Preference: Recommended; ShowFields: YES; ID: 2536; Component_Country_Of_Origin: China
SB2-SB7 SB20 SB25 SB27 SB30 SB35 SB39 SB54 = MCD-00071: Solder Bridge ON; Part_Type: Misc; Manufacturer_Part_Number: RC0603JR-070RL; Manufacturer: YAGEO; Part_Preference: Recommended; ShowFields: YES; ID: 2521; Provided_By: SUBCO
SB8 SB10 SB11 SB13 SB21 SB26 SB33 SB38 SB45 SB48-SB50 SB53 = MCD-00072: Solder Bridge OFF; Part_Type: Misc; Manufacturer_Part_Number: RC0603JR-070RL; Manufacturer: YAGEO; Part_Preference: Recommended; Component_Country_Of_Origin: China; ShowFields: YES; ID: 2520
SB36 = MCD-00071: as SB1 on sheet Power
U9 U10 = MCD-00170: ESD protection 6V1; Part_Type: Diode; Manufacturer: STMICROELECTRONICS; BMS_Part_Number: 9151132; Part_Preference: Recommended; Manufacturer_HQ_COO: EU; Component_Country_Of_Origin: China; ShowFields: YES; ID: 2696; ECCN_US: EAR99; ECCN_EU: NEC; Provided_By: SUBCO with ST control
U13 = MCD-03252: MCU, ARM Cortex-M0+ 32-bit, 256K Flash, 20KB RAM, With Crypto; Part_Type: IC; Part_Preference: Recommended; Manufacturer: STMICROELECTRONICS; ShowFields: YES; ID: 5368
X2 = MCD-01479: Crystal, 32.768kHz, 6pF, +/-20ppm, 80K, 2.05x1.2mm; Part_Type: Crystal_Osc; Manufacturer_Part_Number: NX2012SA-32.768KHZ-EXS00A-MU00527; Manufacturer: NDK; BMS_Part_Number: 9157049; Part_Preference: Recommended; ECCN_US: EAR99; ECCN_EU: NEC; Provided_By: SUBCO; Component_Country_Of_Origin: Unknown; ShowFields: YES; ID: 3579
X3 = MCD-00092: Crystal, 8MHz, 8pF, +/-20ppm, 500R, 3.2x2.5mm; BMS_Part_Number: 9157029; Part_Type: Crystal_Osc; Part_Preference: Recommended; Manufacturer: NDK; Manufacturer_Part_Number: NX3225GD-8MHZ-EXS00A-CG04874; Component_Country_Of_Origin: Unknown; ShowFields: YES; ID: 2776

## Sheet Arduino_Morpho_connectors.SchDoc: Connectors
size A4; CompanyName: STMicroelectronics; Organization: Microcontrollers Division; SheetNumber: 4; SheetTotal: 7
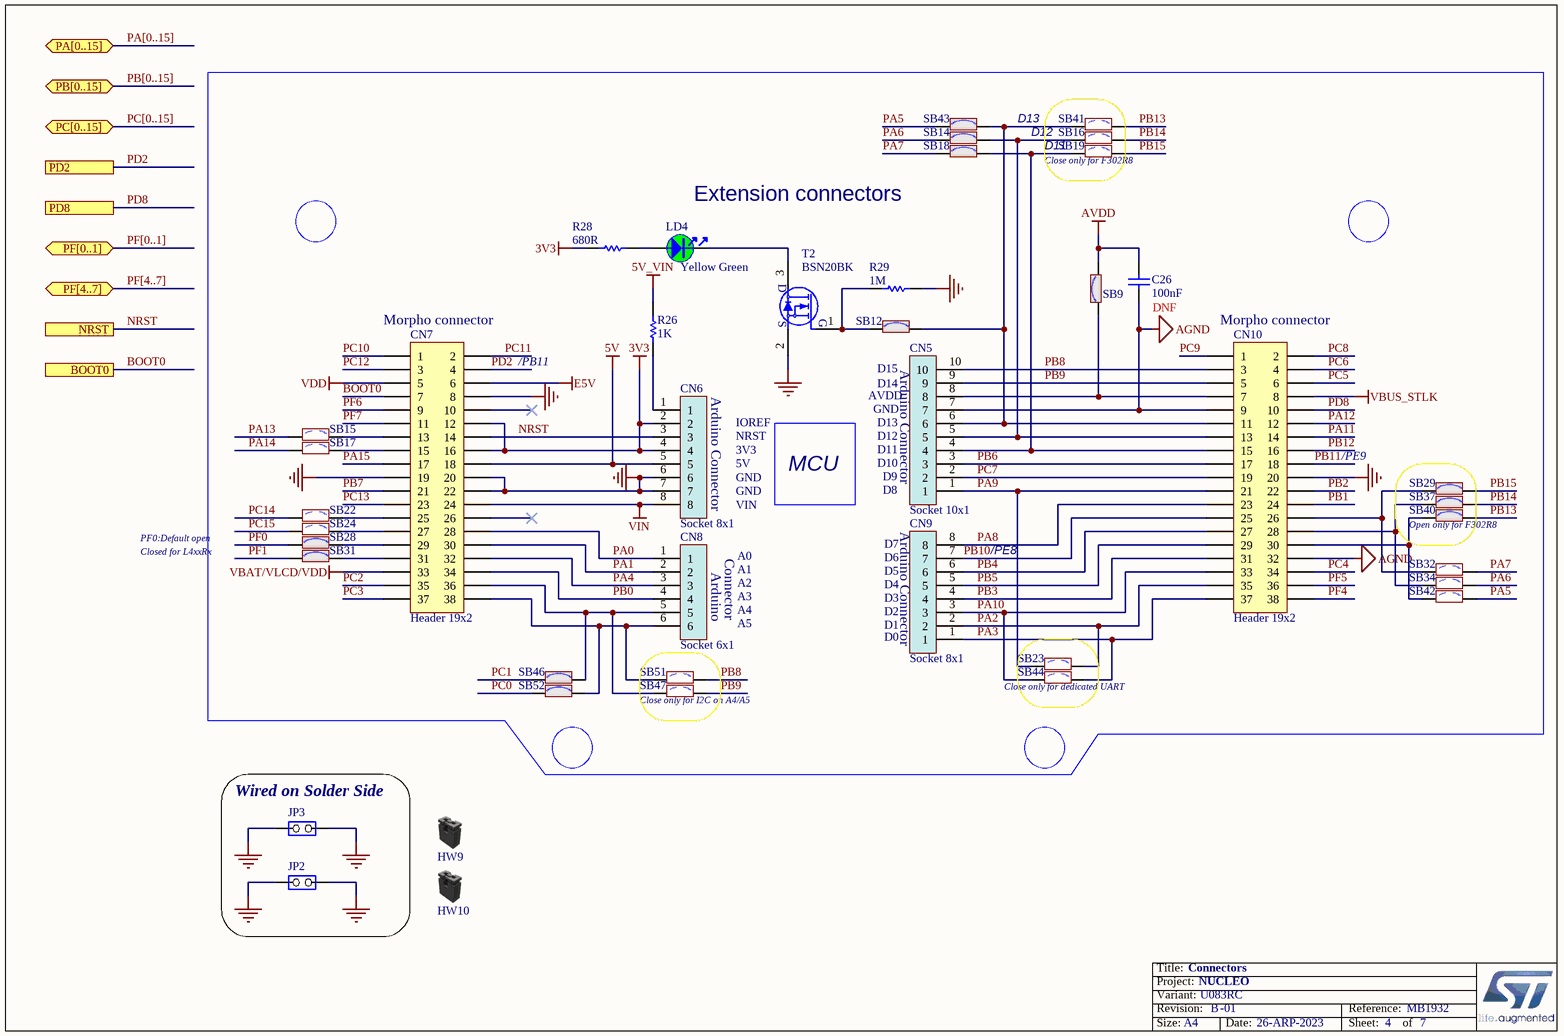
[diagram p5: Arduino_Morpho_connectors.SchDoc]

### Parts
C26  value 100nF  [C0402]  (hidden comment: Capacitor)
CN5  Socket 10x1  [CON_SAMTEC_SSW-110-01-X-S]
CN6  Socket 8x1  [CON_SAMTEC_SSW-108-01-X-S]
CN7  Header 19x2  [CON_SAMTEC_TSW-119-09-X-D]
CN8  Socket 6x1  [CON_SAMTEC_SSW-106-01-X-S]
CN9  Socket 8x1  [CON_SAMTEC_SSW-108-01-X-S]
CN10  Header 19x2  [CON_SAMTEC_TSW-119-09-X-D]
HW9  Shunt Black 2.54mm  (value not drawn)  (mechanical)
HW10  Shunt Black 2.54mm  (value not drawn)  (mechanical)
JP2  Jumper_Header 2x1  [CON_SAMTEC_TSW-102-09-X-S]  (value not drawn)
JP3  Jumper_Header 2x1  [CON_SAMTEC_TSW-102-09-X-S]  (value not drawn)
LD4  value Yellow Green  [LED_0402_EVERLIGHT_16-213SYGC/S530-E3-TR8 _YELLOW-GREEN_1A2K_H0P45]  (hidden comment: LED_green)
R26  value 1K  [R0402]  (hidden comment: Resistor)
R28  value 680R  [R0402]  (hidden comment: Resistor)
R29  value 1M  [R0402]  (hidden comment: Resistor)
SB9  SB_ON  [SOLDER-BRIDGE_R0603-0R]  (value not drawn)
SB12  SB_ON  [SOLDER-BRIDGE_R0603-0R]  (value not drawn)
SB14  SB_ON  [SOLDER-BRIDGE_R0603-0R]  (value not drawn)
SB15  SB_OFF  [SOLDER-BRIDGE_R0603-0R]  (value not drawn)
SB16  SB_OFF  [SOLDER-BRIDGE_R0603-0R]  (value not drawn)
SB17  SB_OFF  [SOLDER-BRIDGE_R0603-0R]  (value not drawn)
SB18  SB_ON  [SOLDER-BRIDGE_R0603-0R]  (value not drawn)
SB19  SB_OFF  [SOLDER-BRIDGE_R0603-0R]  (value not drawn)
SB22  SB_OFF  [SOLDER-BRIDGE_R0603-0R]  (value not drawn)
SB23  SB_OFF  [SOLDER-BRIDGE_R0603-0R]  (value not drawn)
SB24  SB_OFF  [SOLDER-BRIDGE_R0603-0R]  (value not drawn)
SB28  SB_ON  [SOLDER-BRIDGE_R0603-0R]  (value not drawn)
SB29  SB_ON  [SOLDER-BRIDGE_R0603-0R]  (value not drawn)
SB31  SB_ON  [SOLDER-BRIDGE_R0603-0R]  (value not drawn)
SB32  SB_OFF  [SOLDER-BRIDGE_R0603-0R]  (value not drawn)
SB34  SB_OFF  [SOLDER-BRIDGE_R0603-0R]  (value not drawn)
SB37  SB_ON  [SOLDER-BRIDGE_R0603-0R]  (value not drawn)
SB40  SB_ON  [SOLDER-BRIDGE_R0603-0R]  (value not drawn)
SB41  SB_OFF  [SOLDER-BRIDGE_R0603-0R]  (value not drawn)
SB42  SB_OFF  [SOLDER-BRIDGE_R0603-0R]  (value not drawn)
SB43  SB_ON  [SOLDER-BRIDGE_R0603-0R]  (value not drawn)
SB44  SB_OFF  [SOLDER-BRIDGE_R0603-0R]  (value not drawn)
SB46  SB_ON  [SOLDER-BRIDGE_R0603-0R]  (value not drawn)
SB47  SB_OFF  [SOLDER-BRIDGE_R0603-0R]  (value not drawn)
SB51  SB_OFF  [SOLDER-BRIDGE_R0603-0R]  (value not drawn)
SB52  SB_ON  [SOLDER-BRIDGE_R0603-0R]  (value not drawn)
T2  value BSN20BK  [MOS_SOT23]  (hidden comment: BSN20)

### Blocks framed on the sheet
D11: SB16 SB19 SB41
Open only for F302R8: SB29 SB37 SB40
Close only for I2C on A4/A5: SB47 SB51
Wired on Solder Side: JP2 JP3

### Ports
BOOT0, NRST, PA[0..15] (bidir), PB[0..15] (bidir), PC[0..15] (bidir), PD2, PD8, PF[0..1] (bidir), PF[4..7] (bidir)

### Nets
3V3: CN6.2 CN6.4 CN7.12 CN7.16 R28.2
5V: CN6.5 CN7.18
5V_VIN: R26.1
AGND: C26.1 CN5.7 CN10.9 CN10.32
AVDD: C26.2 SB9.2
E5V: CN7.6
GND: CN6.6 CN6.7 CN7.8 CN7.19 CN7.20 CN7.22 CN10.20 JP2.1(COMMON) JP2.2(NO) JP3.1(COMMON) JP3.2(NO) R29.2 T2.2(S)
VBAT/VLCD/VDD: CN7.33
VBUS_STLK: CN10.8
VDD: CN7.5
VIN: CN6.8 CN7.24
BOOT0: CN7.7 ; port BOOT0
NRST: CN6.3 CN7.14 ; port NRST
PA0: CN7.28 CN8.1
PA1: CN7.30 CN8.2
PA2: CN9.2 CN10.35 SB23.2
PA3: CN9.1 CN10.37 SB44.2
PA4: CN7.32 CN8.3
PA5: SB42.2 SB43.1
PA6: SB14.1 SB34.2
PA7: SB18.1 SB32.2
PA8: CN9.8 CN10.23
PA9: CN5.1 CN10.21 SB23.1
PA10: CN9.3 CN10.33 SB44.1
PA11: CN10.14
PA12: CN10.12
PA13: SB15.1  [project net MCU.SWDIO]
PA14: SB17.1  [project net MCU.SWCLK]
PA15: CN7.17
PB0: CN7.34 CN8.4
PB1: CN10.24
PB2: CN10.22
PB3: CN9.4 CN10.31  [project net MCU.SWO]
PB4: CN9.6 CN10.27
PB5: CN9.5 CN10.29
PB6: CN5.3 CN10.17
PB7: CN7.21
PB8: CN5.10 CN10.3 SB51.2
PB9: CN5.9 CN10.5 SB47.2
PB10: CN9.7 CN10.25
PB11: CN10.18
PB12: CN10.16
PB13: SB40.2 SB41.2
PB14: SB16.2 SB37.2
PB15: SB19.2 SB29.2
PC0: SB52.1
PC1: SB46.1
PC2: CN7.35
PC3: CN7.37
PC4: CN10.34
PC5: CN10.6
PC6: CN10.4
PC7: CN5.2 CN10.19
PC8: CN10.2
PC9: CN10.1
PC10: CN7.1
PC11: CN7.2
PC12: CN7.3
PC13: CN7.23
PC14: SB22.1
PC15: SB24.1
PD2: CN7.4 ; port PD2
PD8: CN10.10 ; port PD8
PF0: SB28.1
PF1: SB31.1
PF4: CN10.38
PF5: CN10.36
PF6: CN7.9
PF7: CN7.11
NetCN5_4: CN5.4 CN10.15 SB18.2 SB19.1
NetCN5_5: CN5.5 CN10.13 SB14.2 SB16.1
NetCN5_6: CN5.6 CN10.11 SB12.2 SB41.1 SB43.2
NetCN5_8: CN5.8 CN10.7 SB9.1
NetCN6_1: CN6.1 R26.2
NetCN7_13: CN7.13 SB15.2
NetCN7_15: CN7.15 SB17.2
NetCN7_25: CN7.25 SB22.2
NetCN7_27: CN7.27 SB24.2
NetCN7_29: CN7.29 SB28.2
NetCN7_31: CN7.31 SB31.2
NetCN7_36: CN7.36 CN8.5 SB46.2 SB47.1
NetCN7_38: CN7.38 CN8.6 SB51.1 SB52.2
NetCN10_26: CN10.26 SB29.1 SB32.1
NetCN10_28: CN10.28 SB34.1 SB37.1
NetCN10_30: CN10.30 SB40.1 SB42.1
NetLD4_1: LD4.1 R28.1
NetLD4_2: LD4.2 T2.3(D)
NetR29_1: R29.1 SB12.1 T2.1(G)

Not connected (* = marked no-connect by the designer): CN7 10* 26*

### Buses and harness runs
bus PA[0..15] = port PA[0..15]
bus PB[0..15] = port PB[0..15]
bus PC[0..15] = port PC[0..15]
bus PF[0..1] = port PF[0..1]
bus PF[4..7] = port PF[4..7]

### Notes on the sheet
- D13
- D12
- (near SB19) Close only for F302R8
- Extension connectors
- (near C26) DNF
- (near CN7) Morpho connector
- /PB11
- D15
- Arduino Connector
- (near CN10) Morpho connector
- (near CN6) Arduino Connector
- NRST
- IOREF
- AVDD
- (near CN5) GND
- (near CN5) D12
- (near CN5) D13
- D14
- GND
- VIN
- 5V
- 3V3
- MCU
- (near CN5) D10
- (near CN5) D11
- (near CN5) D9
- D8
- /PE9
- PF0:Default open
- Closed for L4xxRx
- (near CN8) Arduino
- Connector
- A0
- A1
- A2
- (near CN9) D5
- (near CN9) D6
- D7
- (near CN9) Arduino Connector
- /PE8
- A5
- A3
- A4
- (near CN9) D0
- (near CN9) D1
- (near CN9) D2
- (near CN9) D3
- (near CN9) D4
- (near SB44) Close only for dedicated UART

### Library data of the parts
C26 = MCD-00006: as C21 on sheet Power
CN5 = MCD-02080: Socket, 10x1, 2.54mm, VR, TH, T=8.51/2.64mm; Manufacturer_Part_Number: SSW-110-01-G-S; Manufacturer: SAMTEC; Part_Type: Connector; Part_Preference: Recommended; Order_Code_RS: 765-5736; Component_Country_Of_Origin: China, Costa Rica, Malaysia, United States, Vietnam; ShowFields: YES; ID: 4180
CN6 = MCD-01743: Socket, 8x1, 2.54mm, VR, TH, T=8.51/2.64mm; Manufacturer_Part_Number: SSW-108-01-G-S; Manufacturer: SAMTEC; Part_Type: Connector; Part_Preference: Recommended; Order_Code_RS: 765-5698; Component_Country_Of_Origin: China, Costa Rica, Malaysia, United States, Vietnam; ShowFields: YES; ID: 3843
CN7 CN10 = MCD-00213: Header, 19x2, 2.54mm, VR, TH, T=5.84mm/10.16mm; Manufacturer_Part_Number: TSW-119-09-G-D; Manufacturer: SAMTEC; Part_Type: Connector; Part_Preference: Recommended; Provided_By: SUBCO; Component_Country_Of_Origin: China, Costa Rica, Malaysia, United States, Vietnam; ShowFields: YES; ID: 2656
CN8 = MCD-02079: Socket, 6x1, 2.54mm, VR, TH, T=8.51/2.64mm; Part_Type: Connector; Manufacturer_Part_Number: SSW-106-01-G-S; Manufacturer: SAMTEC; Part_Preference: Recommended; Order_Code_RS: 765-5666; Component_Country_Of_Origin: China, Costa Rica, Malaysia, United States, Vietnam; ShowFields: YES; ID: 4179
CN9 = MCD-01743: Socket, 8x1, 2.54mm, VR, TH, T=8.51/2.64mm; Part_Type: Connector; Manufacturer_Part_Number: SSW-108-01-G-S; Manufacturer: SAMTEC; Part_Preference: Recommended; Order_Code_RS: 765-5698; Component_Country_Of_Origin: China, Costa Rica, Malaysia, United States, Vietnam; ShowFields: YES; ID: 3843
HW9 HW10 = MCD-00043: as HW3 on sheet Power
JP2 JP3 = MCD-00214: Header, 2x1, 2,54mm, VR, TH, Height 5.84mm/10.16mm; Part_Type: Connector; Manufacturer_Part_Number: TSW-102-09-G-S; Manufacturer: SAMTEC; Part_Preference: Recommended; Value: Header 2x1 16mm
LD4 = MCD-02330: as LD3 on sheet Power
R26 = MCD-00061: Resistor, 1K, 0402, +/-1%,1/16W; Manufacturer_Part_Number: RC0402FR-071KL; Manufacturer: YAGEO; Alternate_Manufacturer_Part_Number: RT0402FRE07100KL; Part_Preference: Recommended; ECCN_US: EAR99; ECCN_EU: NEC; Provided_By: SUBCO; Component_Country_Of_Origin: China; ShowFields: YES; ID: 2532
R28 = MCD-00507: as R30 on sheet Power
R29 = MCD-00182: Resistor, 1M, 0402, +/-1%, 1/16W; Manufacturer_Part_Number: RC0402FR-071ML; Manufacturer: YAGEO; Alternate_Manufacturer_Part_Number: RT0402FRE07100KL; Part_Preference: Recommended; BMS_Part_Number: 9131778; ECCN_US: EAR99; ECCN_EU: NEC; Provided_By: SUBCO; Order_Code_RS: 618-6194; Component_Country_Of_Origin: China; ShowFields: YES; ID: 2686
SB9 = MCD-00071: Solder Bridge ON; Part_Type: Misc; Manufacturer_Part_Number: RC0603JR-070RL; Manufacturer: YAGEO; Part_Preference: Recommended; ShowFields: YES; ID: 2521
SB12 SB46 SB52 = MCD-00071: as SB1 on sheet Power
SB14 SB18 SB28 SB29 SB31 SB37 SB40 SB43 = MCD-00071: as SB2 on sheet STM32_microcontroller_IOs
SB15-SB17 SB19 SB22-SB24 SB32 SB34 SB41 SB42 SB44 SB47 SB51 = MCD-00072: as SB8 on sheet STM32_microcontroller_IOs
T2 = MCD-01969: Transistor, N-channel enhancement mode field-effect transistor; Manufacturer: NEXPERIA; Part_Preference: Recommended; Order_Code_RS: 136-4845; Component_Country_Of_Origin: China; ShowFields: YES; ID: 4069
